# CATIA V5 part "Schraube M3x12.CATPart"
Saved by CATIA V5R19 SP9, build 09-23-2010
Part number: Schraube M3x12
Bounding box of the stored display mesh (mm): x -2.948 to 2.948, y -2.975 to 2.975, z -12 to 2
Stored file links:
  D:\Temporäre Sachen\Lasermodul KY-008 with mounting for adjustment\Schraube M3x12.CATPart
  d:\Program Files\Dassault Systemes\B19\win_b64\reffiles\standard\MetricThickPitch.txt
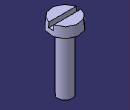
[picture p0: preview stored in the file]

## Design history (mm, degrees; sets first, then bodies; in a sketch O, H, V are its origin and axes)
Body1 (main body)
  Sketch1 on yz-plane, origin (0, 0, 0), H (0, 1, 0), V (0, 0, 1)
    axis line L1 (0, -35.7308) -> (0, 90.3306)
    point P1 (0, -35.7308)
    point P3 (0, 2)
    line L2 (0, 2) -> (2.825, 2)
    line L3 (2.825, 2) -> (3, 0)
    point P5 (3, 0)
    line L4 (3, 0) -> (1.5, 0)
    line L5 (1.5, 0) -> (1.5, -12)
    line L6 (1.5, -12) -> (0, -12)
    point P8 (0, -12)
    distance L5 L1 = 1.5
    distance L4 L6 = 12
    distance L4 L2 = 2
    distance L1 P5 = 3
    angle L3 L1 = 5
    coincidence: P1 V, P3 L1, P5 H, P8 L1
    vertical: L1 V, L5 V
    horizontal: L2 H, L4 H, L6 H
  Shaft1: profile Sketch1, axis Sketch1.L1, angle 360
  Sketch2 on xy-plane, origin (0, 0, 0), H (1, 0, 0), V (0, 1, 0)
    line L1 (5, 0.5) -> (5, -0.5)
    line L2 (5, -0.5) -> (-5, -0.5)
    line L3 (-5, -0.5) -> (-5, 0.5)
    line L4 (-5, 0.5) -> (5, 0.5)
    distance L2 L4 = 1
    distance L1 L3 = 10
    vertical: L1 V, L3 V
    horizontal: L2 H, L4 H
    equidistance: L1 L3 O, L2 L4 O
  Pocket1: profile Sketch2, direction (0, 0, 1), length 20, opposite side length -1
  Thread1: "M3", diameter 3, depth 8, pitch 0.5, on face of Shaft1 from Sketch1.L5, from face of Shaft1 from Sketch1.L6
